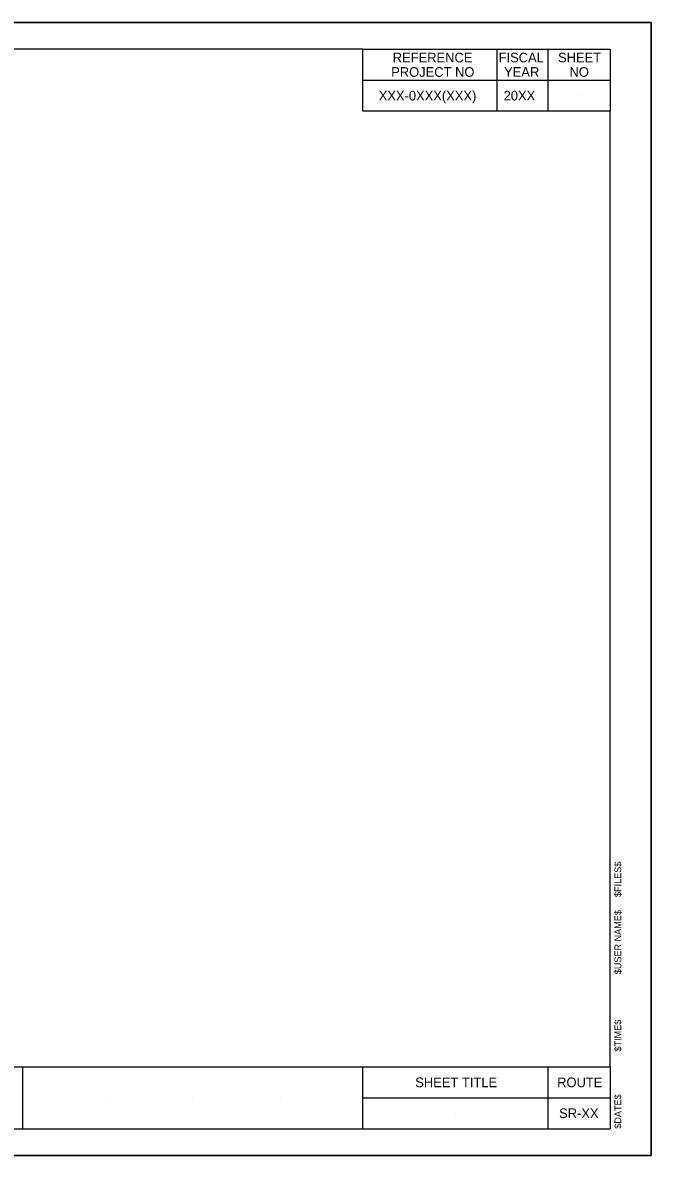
# Model space of a CAD drawing. Extents: x 0 to 6800, y 0 to 4400.
# Drawn here: x 4360 to 6800, y 0 to 4400 of the extents above; entities that cross this region are included whole.
import ezdxf

# ---------------------------------------------------------------- set-up
doc = ezdxf.new("R2010")
doc.units = 0
for name, color, linetype in [('ANNO-SHT', 7, 'Continuous'), ('SHT-BDR', 7, 'Continuous'), ('SHT-FENCE', 7, 'Continuous')]:
    doc.layers.add(name, color=color, linetype=linetype)

msp = doc.modelspace()

# ---------------------------------------------------------------- linework, layer by layer
at = {"layer": 'ANNO-SHT'}
msp.add_line((6040, 163.5), (6040, 163.5), dxfattribs=at)
msp.add_line((6040, 163.5), (6040, 163.5), dxfattribs=at)
at = {"layer": 'SHT-BDR'}
for p, q in [((5680, 4296.5), (6640, 4296.5)), ((6202, 4056.5), (6202, 4296.5)), ((6400, 4056.5), (6400, 4296.5)), ((6640, 4296.5), (6640, 4056.5)), ((5680, 4176.5), (6640, 4176.5)), ((5944, 4116.5), (5944, 4116.5)), ((5944, 4116.5), (5944, 4116.5)), ((6304, 4116.5), (6304, 4116.5)), ((6304, 4116.5), (6304, 4116.5)), ((6520, 4116.5), (6520, 4116.5)), ((6520, 4116.5), (6520, 4116.5)), ((4360, 103.5), (4360, 343.5)), ((5680, 103.5), (5680, 343.5)), ((6400, 103.5), (6400, 343.5)), ((6640, 343.5), (6640, 103.5)), ((4680, 223.5), (4680, 223.5)), ((4680, 223.5), (4680, 223.5)), ((5020, 223.5), (5020, 223.5)), ((5020, 223.5), (5020, 223.5)), ((5360, 223.5), (5360, 223.5)), ((5360, 223.5), (5360, 223.5)), ((5680, 223.5), (6640, 223.5)), ((6520, 163.5), (6520, 163.5)), ((6520, 163.5), (6520, 163.5)), ((160, 103.5), (6640, 103.5))]:
    msp.add_line(p, q, dxfattribs=at)
for points in [[(0, 0), (6800, 0), (6800, 4400), (0, 4400)], [(160, 4296.5), (160, 343.5), (6640, 343.5), (6640, 4056.5), (5680, 4056.5), (5680, 4296.5)]]:
    msp.add_lwpolyline(points, close=True, dxfattribs=at)
at = {"layer": 'SHT-FENCE'}
msp.add_lwpolyline([(0, 4400), (6800, 4400), (6800, 0), (0, 0)], close=True, dxfattribs=at)

# ---------------------------------------------------------------- texts
at = {"layer": 'ANNO-SHT'}
for s, p in [('REFERENCE', (5796.4, 4245.8)), ('FISCAL', (6207.3, 4245.8)), ('SHEET', (6437.8, 4245.8)), ('PROJECT NO', (5790.3, 4189.6)), ('YEAR', (6228.5, 4189.6)), ('NO', (6482.4, 4189.6)), ('XXX-0XXX(XXX)', (5741.9, 4097.7)), ('20XX', (6226.8, 4097.7)), ('SHEET TITLE', (5883.7, 264.8)), ('ROUTE', (6434.5, 264.8)), ('SR-XX', (6442.1, 144.8))]:
    msp.add_text(s, height=37.5, dxfattribs=at).set_placement(p)
for s, p in [('$FILES$', (6683.2, 1003.5)), ('$USER NAME$', (6683.2, 703.5)), ('$TIME$', (6683.2, 403.5)), ('$DATE$', (6683.2, 103.5))]:
    msp.add_text(s, height=26.4, rotation=90, dxfattribs=at).set_placement(p)

doc.saveas('drawing.dxf')
